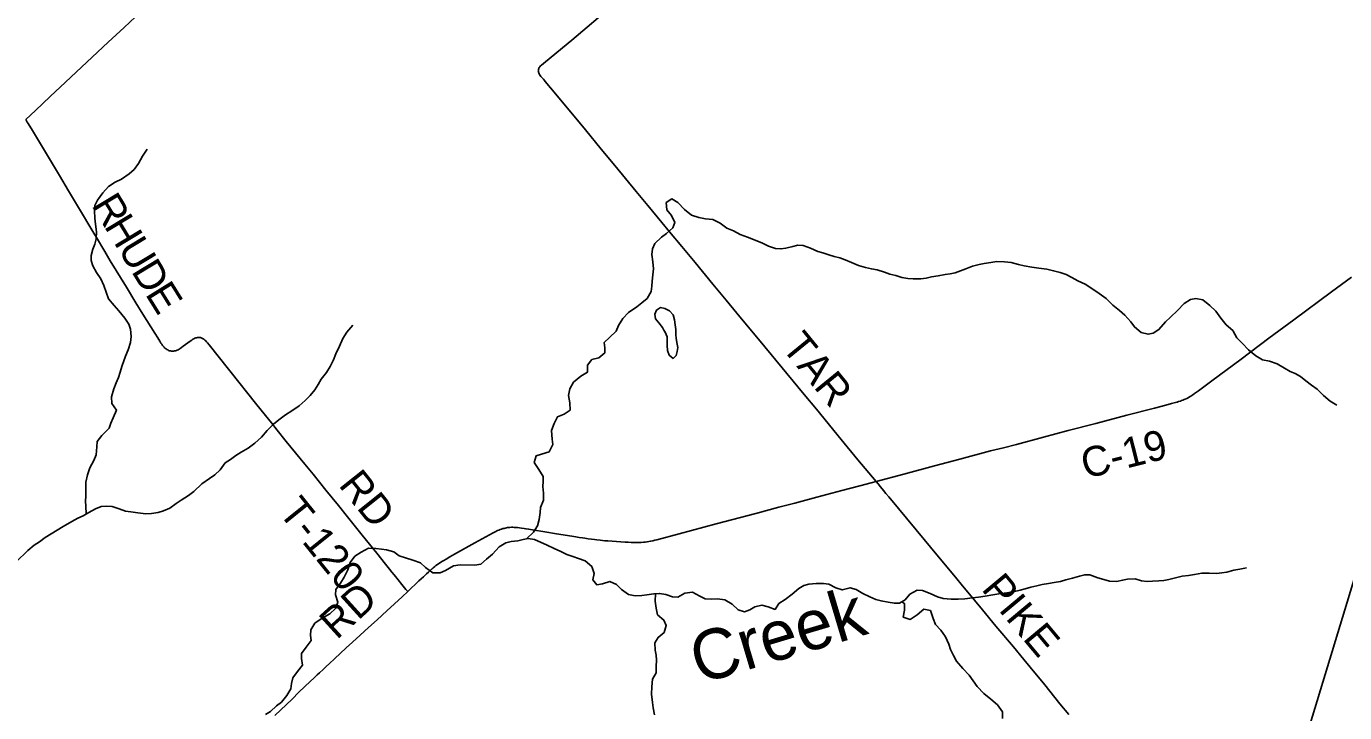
# Model space of a CAD drawing. Extents: x 1442749 to 1756758, y 235267 to 677782.
# Drawn here: x 1552947 to 1566168, y 481611 to 488495 of the extents above; entities that cross this region are included whole.
import ezdxf

# ---------------------------------------------------------------- set-up
doc = ezdxf.new("R2010")
doc.units = 0
for name, color, linetype in [('GM_X_County_Road', 7, 'Continuous'), ('GM_X_County_Road_Text', 7, 'Continuous'), ('GM_X_Minor_Lake', 7, 'Continuous'), ('GM_X_Minor_River', 7, 'Continuous'), ('GM_X_Minor_River_Text', 7, 'Continuous'), ('GM_X_State_Route', 7, 'Continuous'), ('GM_X_Township', 7, 'Continuous'), ('GM_X_Township_Road', 7, 'Continuous'), ('GM_X_Township_Road_Text', 7, 'Continuous')]:
    doc.layers.add(name, color=color, linetype=linetype)

msp = doc.modelspace()

# ---------------------------------------------------------------- linework, layer by layer
at = {"layer": 'GM_X_County_Road'}
for points in [[(1561468, 483929), (1561285, 484147), (1561119, 484350), (1560870, 484655), (1560748, 484801), (1560354, 485280), (1560073, 485618), (1559964, 485749), (1559833, 485909), (1559653, 486126), (1559519, 486288), (1559398, 486435), (1559321, 486529), (1559180, 486698), (1559064, 486840), (1558849, 487101), (1558713, 487265), (1558554, 487457), (1558257, 487815), (1558151, 487941), (1558142, 487952), (1558132, 487964), (1558119, 487979), (1558106, 487994), (1558100, 488003), (1558094, 488011), (1558089, 488020), (1558085, 488028), (1558083, 488035), (1558082, 488042), (1558081, 488050), (1558082, 488057), (1558083, 488063), (1558085, 488071), (1558088, 488077), (1558091, 488082), (1558096, 488089), (1558103, 488098), (1558113, 488106), (1558154, 488141), (1558416, 488358), (1558836, 488712)], [(1561468, 483929), (1561746, 484004), (1562056, 484086), (1562310, 484153), (1562617, 484236), (1562745, 484268), (1562878, 484302), (1563148, 484373), (1563394, 484442), (1563671, 484513), (1563982, 484595), (1564262, 484667), (1564375, 484697), (1564433, 484711), (1564458, 484718), (1564472, 484722), (1564488, 484726), (1564502, 484731), (1564520, 484736), (1564531, 484741), (1564545, 484746), (1564558, 484751), (1564570, 484756), (1564584, 484763), (1564598, 484770), (1564612, 484778), (1564624, 484785), (1564634, 484792), (1564646, 484799), (1564663, 484811), (1564702, 484839), (1564837, 484939), (1565130, 485158), (1565408, 485367), (1565659, 485553), (1566036, 485831), (1566237, 485980)], [(1557010, 483050), (1557012, 483052), (1557027, 483064), (1557043, 483077), (1557055, 483086), (1557069, 483096), (1557082, 483106), (1557099, 483117), (1557115, 483128), (1557134, 483139), (1557156, 483152), (1557193, 483173), (1557241, 483200), (1557445, 483313), (1557628, 483415), (1557649, 483426), (1557673, 483437), (1557686, 483443), (1557697, 483447), (1557711, 483452), (1557726, 483457), (1557738, 483460), (1557749, 483463), (1557761, 483465), (1557771, 483467), (1557782, 483468), (1557794, 483470), (1557811, 483471), (1557825, 483471), (1557838, 483470), (1557854, 483469), (1557872, 483468), (1557891, 483465), (1557913, 483462), (1557938, 483459), (1557957, 483456), (1557985, 483451), (1558002, 483449), (1558024, 483445), (1558146, 483426), (1558263, 483406), (1558416, 483381), (1558459, 483374), (1558492, 483369), (1558523, 483364), (1558549, 483360), (1558580, 483356), (1558615, 483351), (1558643, 483347), (1558669, 483344), (1558700, 483341), (1558725, 483338), (1558749, 483336), (1558778, 483334), (1558823, 483331), (1558866, 483328), (1558953, 483322), (1558982, 483320), (1559011, 483318), (1559034, 483317), (1559050, 483317), (1559069, 483317), (1559092, 483318), (1559114, 483319), (1559136, 483321), (1559153, 483322), (1559171, 483324), (1559188, 483327), (1559207, 483331), (1559229, 483336), (1559249, 483340), (1559271, 483346), (1559494, 483405), (1559864, 483504), (1560262, 483609), (1560493, 483671), (1560655, 483714), (1560876, 483774), (1561124, 483840), (1561305, 483886), (1561419, 483916), (1561468, 483929)], [(1563401, 481593), (1563311, 481701), (1563160, 481891), (1563114, 481947), (1563076, 481992), (1562951, 482144), (1562846, 482270), (1562671, 482479), (1562535, 482643), (1562472, 482718), (1562353, 482863), (1562248, 482989), (1562095, 483173), (1561869, 483446), (1561597, 483775), (1561567, 483810), (1561542, 483840), (1561514, 483875), (1561488, 483906), (1561468, 483929)], [(1556772, 482825), (1556884, 482932), (1556928, 482974), (1556959, 483004), (1556979, 483022), (1556995, 483036), (1557010, 483050)], [(1555438, 481581), (1555611, 481747), (1555681, 481815), (1555740, 481873), (1555793, 481922), (1555833, 481960), (1555863, 481989), (1555888, 482012), (1555922, 482043), (1555954, 482073), (1555986, 482104), (1556037, 482151), (1556154, 482260), (1556217, 482317), (1556294, 482388), (1556377, 482464), (1556465, 482543), (1556562, 482632), (1556717, 482773), (1556772, 482825)]]:
    msp.add_lwpolyline(points, dxfattribs=at)
at = {"layer": 'GM_X_Minor_Lake'}
for points in [[(1559460, 485402), (1559460, 485454), (1559452, 485500), (1559447, 485552), (1559434, 485602), (1559398, 485641), (1559349, 485666), (1559307, 485674), (1559266, 485649), (1559250, 485609), (1559257, 485563), (1559289, 485522), (1559326, 485473), (1559341, 485448)], [(1559341, 485448), (1559353, 485427), (1559373, 485381), (1559374, 485338), (1559373, 485294), (1559377, 485244), (1559392, 485198), (1559432, 485165), (1559462, 485193), (1559475, 485233), (1559481, 485275), (1559472, 485323), (1559465, 485369), (1559460, 485402)]]:
    msp.add_lwpolyline(points, dxfattribs=at)
at = {"layer": 'GM_X_Minor_River'}
for points in [[(1553548, 483604), (1553542, 483682), (1553541, 483734), (1553544, 483784), (1553543, 483854), (1553544, 483922), (1553559, 483998), (1553582, 484066), (1553623, 484142), (1553646, 484198), (1553655, 484276), (1553656, 484330), (1553705, 484391), (1553776, 484464), (1553795, 484516), (1553817, 484568), (1553850, 484644), (1553805, 484713), (1553800, 484779), (1553825, 484859), (1553846, 484918), (1553871, 484974), (1553886, 485028), (1553905, 485082), (1553942, 485186), (1553967, 485250), (1553992, 485323), (1553999, 485385), (1553992, 485458), (1553975, 485508), (1553936, 485569), (1553873, 485642), (1553827, 485694), (1553772, 485763), (1553747, 485830), (1553724, 485896), (1553695, 485963), (1553650, 486026), (1553613, 486092), (1553598, 486147), (1553598, 486197), (1553613, 486259), (1553632, 486310), (1553647, 486364), (1553650, 486435), (1553639, 486511), (1553632, 486571), (1553631, 486645), (1553634, 486697), (1553659, 486751), (1553714, 486825), (1553771, 486888), (1553837, 486931), (1553900, 486962), (1553977, 487017), (1554027, 487059), (1554070, 487120), (1554111, 487194), (1554158, 487262)], [(1557961, 483355), (1558033, 483422), (1558072, 483486), (1558089, 483550), (1558100, 483620), (1558103, 483670), (1558132, 483742), (1558133, 483814), (1558126, 483878), (1558129, 483930), (1558131, 483980), (1558088, 484051), (1558041, 484120), (1558058, 484188), (1558114, 484203), (1558189, 484228), (1558226, 484300), (1558219, 484356), (1558212, 484442), (1558239, 484512), (1558274, 484580), (1558342, 484605), (1558399, 484646), (1558396, 484720), (1558383, 484793), (1558396, 484859), (1558433, 484926), (1558506, 484987), (1558573, 485025), (1558574, 485097), (1558619, 485154), (1558687, 485169), (1558748, 485219), (1558748, 485271), (1558741, 485323), (1558796, 485374), (1558861, 485438), (1558884, 485495), (1558929, 485565), (1558986, 485626), (1559069, 485683), (1559119, 485723), (1559174, 485766), (1559213, 485836), (1559218, 485888), (1559223, 485940), (1559229, 486004), (1559236, 486062), (1559231, 486132), (1559220, 486207), (1559225, 486265), (1559250, 486316), (1559317, 486382), (1559368, 486417), (1559431, 486476), (1559449, 486528), (1559418, 486597), (1559369, 486654), (1559362, 486728), (1559421, 486765), (1559482, 486730), (1559547, 486659), (1559616, 486600), (1559690, 486577), (1559758, 486566), (1559830, 486557), (1559904, 486522), (1559971, 486471), (1560039, 486444), (1560106, 486409), (1560180, 486382), (1560256, 486349), (1560329, 486320), (1560389, 486289), (1560461, 486268), (1560515, 486263), (1560565, 486272), (1560635, 486288), (1560685, 486299), (1560739, 486298), (1560811, 486271), (1560885, 486236), (1560936, 486223), (1560994, 486205), (1561048, 486188), (1561106, 486173), (1561160, 486154), (1561223, 486127), (1561291, 486096), (1561361, 486075), (1561421, 486062), (1561480, 486054), (1561554, 486031), (1561606, 486010), (1561668, 485995), (1561728, 485976), (1561788, 485965), (1561842, 485962), (1561916, 485962), (1561970, 485969), (1562024, 485982)], [(1562024, 485982), (1562092, 485993), (1562160, 486006), (1562211, 486012), (1562261, 486023), (1562315, 486042), (1562368, 486062), (1562436, 486089), (1562502, 486106), (1562552, 486115), (1562621, 486126), (1562681, 486136), (1562755, 486133), (1562823, 486126), (1562897, 486107), (1562955, 486094), (1563030, 486081), (1563100, 486070), (1563180, 486061), (1563248, 486044), (1563316, 486025), (1563376, 486006), (1563431, 485975), (1563493, 485942), (1563564, 485909), (1563632, 485866), (1563707, 485815), (1563775, 485764), (1563844, 485699), (1563911, 485644), (1563962, 485599), (1564024, 485532), (1564059, 485481), (1564126, 485424), (1564196, 485407), (1564246, 485419), (1564305, 485454), (1564370, 485531), (1564421, 485579), (1564492, 485644), (1564559, 485715), (1564623, 485756), (1564674, 485764), (1564747, 485751), (1564817, 485696), (1564876, 485637), (1564927, 485568), (1564980, 485503), (1565045, 485446), (1565086, 485371), (1565140, 485316), (1565203, 485251), (1565276, 485190), (1565345, 485149), (1565413, 485138), (1565491, 485109), (1565564, 485068), (1565620, 485033), (1565672, 485012), (1565725, 484982), (1565779, 484939), (1565834, 484896), (1565892, 484855), (1565957, 484792), (1566022, 484737), (1566089, 484694)], [(1554889, 484048), (1554942, 484116), (1554994, 484149), (1555047, 484191), (1555100, 484224), (1555170, 484265), (1555237, 484314), (1555306, 484375), (1555361, 484443), (1555424, 484504), (1555479, 484549), (1555545, 484599), (1555608, 484640), (1555683, 484689), (1555744, 484742), (1555793, 484794), (1555839, 484851), (1555874, 484903), (1555905, 484957), (1555956, 485022), (1555995, 485082), (1556026, 485149), (1556049, 485209), (1556086, 485287), (1556119, 485363), (1556162, 485428), (1556221, 485498)], [(1552846, 483124), (1552963, 483239), (1553024, 483290), (1553077, 483325), (1553137, 483369), (1553196, 483406), (1553257, 483443), (1553315, 483480), (1553404, 483529), (1553464, 483563), (1553517, 483586), (1553573, 483619), (1553640, 483654), (1553696, 483678), (1553753, 483683), (1553806, 483678), (1553876, 483657), (1553940, 483632), (1553994, 483624), (1554064, 483615), (1554144, 483607), (1554202, 483609), (1554268, 483620), (1554322, 483635), (1554387, 483662), (1554450, 483708), (1554500, 483743), (1554573, 483790), (1554628, 483831), (1554707, 483908), (1554782, 483960), (1554836, 483997), (1554889, 484048)], [(1555454, 481681), (1555504, 481717), (1555559, 481784), (1555600, 481850), (1555605, 481904), (1555620, 481960), (1555665, 482023), (1555716, 482089), (1555707, 482153), (1555705, 482203), (1555754, 482267), (1555803, 482334), (1555796, 482386), (1555799, 482442), (1555840, 482508), (1555913, 482559), (1555989, 482602), (1556048, 482655), (1556069, 482719), (1556046, 482794), (1556051, 482848), (1556096, 482911), (1556135, 482971), (1556170, 483045), (1556193, 483117), (1556242, 483182), (1556304, 483221), (1556379, 483260), (1556453, 483259), (1556507, 483251), (1556559, 483244), (1556631, 483223), (1556686, 483184), (1556750, 483165), (1556822, 483142), (1556898, 483113), (1556951, 483066), (1557022, 483015), (1557096, 483012), (1557149, 483037), (1557231, 483084), (1557296, 483094), (1557444, 483092), (1557506, 483099), (1557563, 483152), (1557622, 483201), (1557687, 483275), (1557757, 483316), (1557808, 483327), (1557876, 483336), (1557928, 483348), (1557978, 483359), (1558044, 483348), (1558169, 483292), (1558241, 483259), (1558307, 483228), (1558368, 483199), (1558428, 483178), (1558484, 483158), (1558551, 483133), (1558619, 483076), (1558642, 483007), (1558627, 482945), (1558668, 482894), (1558726, 482902), (1558797, 482927), (1558864, 482898), (1558914, 482845), (1558985, 482796), (1559053, 482783), (1559119, 482786), (1559171, 482793), (1559241, 482803), (1559298, 482808), (1559361, 482797), (1559427, 482774), (1559479, 482771), (1559552, 482810), (1559626, 482821), (1559702, 482778), (1559753, 482753), (1559813, 482751), (1559879, 482752), (1559953, 482743), (1560025, 482700), (1560086, 482641), (1560148, 482622), (1560202, 482643), (1560253, 482671), (1560323, 482690), (1560387, 482673), (1560456, 482646), (1560493, 482705), (1560558, 482747), (1560627, 482800), (1560694, 482857), (1560744, 482886), (1560794, 482900), (1560869, 482905), (1560941, 482908), (1560995, 482901)], [(1560995, 482901), (1561066, 482864), (1561130, 482843), (1561208, 482864), (1561268, 482847), (1561336, 482808), (1561407, 482773), (1561467, 482746), (1561519, 482732), (1561589, 482721), (1561653, 482708), (1561703, 482709), (1561759, 482742), (1561808, 482798), (1561879, 482839), (1561935, 482836), (1562012, 482805), (1562086, 482774), (1562140, 482757), (1562220, 482750), (1562292, 482751), (1562360, 482754), (1562436, 482763), (1562496, 482770), (1562562, 482779), (1562639, 482792), (1562701, 482802), (1562779, 482813), (1562845, 482824), (1562912, 482839), (1562964, 482852), (1563022, 482869), (1563080, 482883), (1563135, 482896), (1563197, 482905), (1563255, 482916), (1563319, 482928), (1563372, 482943), (1563438, 482960), (1563510, 482981), (1563561, 482994), (1563613, 482994), (1563692, 482963), (1563752, 482946), (1563808, 482931), (1563884, 482928), (1563940, 482939), (1563990, 482949), (1564066, 482952), (1564132, 482935), (1564188, 482928), (1564240, 482929), (1564304, 482932), (1564354, 482936), (1564405, 482947), (1564471, 482962), (1564539, 482981), (1564601, 482988), (1564662, 482996), (1564736, 483009), (1564808, 483010), (1564882, 483007), (1564936, 483012), (1564986, 483019), (1565057, 483040), (1565117, 483052), (1565185, 483065)], [(1559255, 482804), (1559252, 482728), (1559263, 482658), (1559276, 482594), (1559340, 482539), (1559365, 482484), (1559344, 482416), (1559283, 482365), (1559250, 482313), (1559253, 482239), (1559263, 482187), (1559266, 482137), (1559263, 482073), (1559262, 482010), (1559227, 481947), (1559218, 481871), (1559217, 481797), (1559226, 481714), (1559233, 481658), (1559246, 481588)], [(1561729, 482724), (1561755, 482704), (1561752, 482640), (1561741, 482570), (1561810, 482547), (1561881, 482592), (1561948, 482648), (1562014, 482635), (1562041, 482556), (1562064, 482494), (1562117, 482439), (1562164, 482370), (1562199, 482297), (1562214, 482243), (1562244, 482186), (1562275, 482126), (1562340, 482055), (1562401, 481986), (1562483, 481872), (1562550, 481803), (1562620, 481748), (1562685, 481691), (1562736, 481620), (1562735, 481554)], [(1555344, 481593), (1555395, 481624), (1555454, 481681)]]:
    msp.add_lwpolyline(points, dxfattribs=at)
at = {"layer": 'GM_X_State_Route'}
msp.add_lwpolyline([(1552940, 487560), (1553038, 487652), (1553186, 487792), (1553340, 487935), (1553767, 488338), (1553926, 488485), (1554041, 488592), (1554164, 488711)], dxfattribs=at)
at = {"layer": 'GM_X_Township'}
for points in [[(1570793, 458137), (1565757, 458561), (1558990, 459152), (1560357, 463622), (1560897, 465383), (1561114, 466092), (1562630, 471037), (1563836, 475001), (1564414, 476901), (1565133, 479233), (1565146, 479277), (1565221, 479519), (1566747, 484545)], [(1566747, 484545), (1565221, 479519)]]:
    msp.add_lwpolyline(points, dxfattribs=at)
at = {"layer": 'GM_X_Township_Road'}
msp.add_lwpolyline([(1556772, 482825), (1556754, 482848), (1556637, 482993), (1556613, 483022), (1556589, 483051), (1556549, 483100), (1556461, 483211), (1556315, 483393), (1556167, 483576), (1556078, 483690), (1555951, 483843), (1555823, 484002), (1555740, 484104), (1555554, 484331), (1555463, 484445), (1555405, 484518), (1555346, 484592), (1555246, 484716), (1555000, 485024), (1554843, 485220), (1554820, 485250), (1554793, 485283), (1554780, 485300), (1554763, 485320), (1554753, 485331), (1554746, 485340), (1554737, 485348), (1554728, 485356), (1554720, 485361), (1554714, 485365), (1554707, 485368), (1554700, 485371), (1554692, 485373), (1554682, 485374), (1554671, 485374), (1554662, 485373), (1554654, 485372), (1554646, 485370), (1554636, 485366), (1554627, 485361), (1554617, 485356), (1554606, 485348), (1554589, 485336), (1554521, 485286), (1554503, 485273), (1554489, 485263), (1554479, 485258), (1554468, 485252), (1554459, 485248), (1554451, 485245), (1554444, 485242), (1554433, 485239), (1554422, 485238), (1554413, 485237), (1554404, 485238), (1554392, 485239), (1554382, 485241), (1554373, 485245), (1554365, 485249), (1554357, 485253), (1554349, 485259), (1554341, 485265), (1554333, 485272), (1554328, 485278), (1554321, 485285), (1554313, 485295), (1554305, 485307), (1554297, 485319), (1554286, 485337), (1554265, 485370), (1554236, 485418), (1554116, 485610), (1554046, 485721), (1553950, 485879), (1553788, 486143), (1553761, 486189), (1553733, 486238), (1553704, 486286), (1553679, 486328), (1553604, 486454), (1553489, 486645), (1553370, 486845), (1553278, 487000), (1553067, 487352), (1552997, 487467), (1552974, 487505), (1552965, 487521), (1552956, 487534), (1552940, 487560)], dxfattribs=at)

# ---------------------------------------------------------------- texts
at = {"layer": 'GM_X_County_Road_Text'}
for s, rotation, p in [('TAR', 309.2402, (1560511, 485275)), ('C-19', 14.2028, (1563568, 483955)), ('PIKE', 309.8779, (1562517, 482848)), ('RD', 42.2078, (1556059, 482336))]:
    msp.add_text(s, height=300, rotation=rotation, dxfattribs=at).set_placement(p)
at = {"layer": 'GM_X_Minor_River_Text'}
msp.add_text('Creek', height=500, rotation=16.626, dxfattribs=at).set_placement((1559696, 481894))
at = {"layer": 'GM_X_Township_Road_Text'}
for s, rotation, p in [('R', 301.1432, (1553594, 486703)), ('H', 301.1412, (1553721, 486492)), ('U', 301.1427, (1553858, 486266)), ('D', 301.1687, (1553994, 486040)), ('E', 301.8414, (1554133, 485811)), ('RD', 308.66, (1556070, 483892)), ('T-120', 308.8349, (1555466, 483621))]:
    msp.add_text(s, height=300, rotation=rotation, dxfattribs=at).set_placement(p)

doc.saveas('drawing.dxf')
